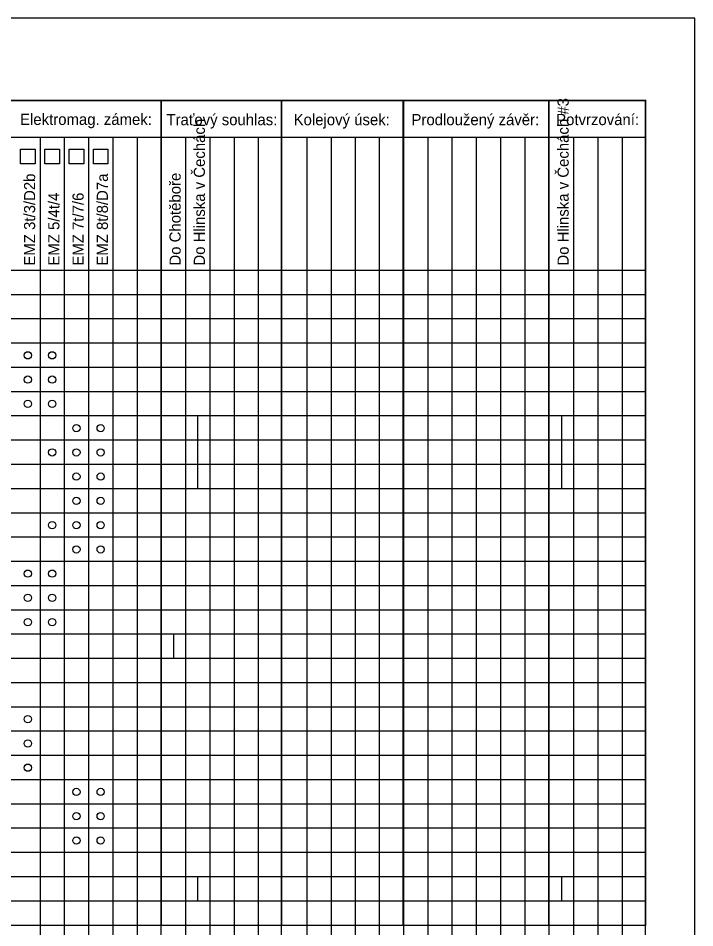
# Model space of a CAD drawing. Extents: x 2343 to 5155, y -3940 to 2050.
# Drawn here: x 4830.5 to 4970, y -3830.5 to -3643 of the extents above; entities that cross this region are included whole.
import ezdxf

# ---------------------------------------------------------------- set-up
doc = ezdxf.new("R2010")
doc.units = 0
for name, color, linetype in [('0B', 7, 'Continuous'), ('Vrstva 1', 7, 'Continuous'), ('Vrstva 63', 7, 'Continuous')]:
    doc.layers.add(name, color=color, linetype=linetype)

# ---------------------------------------------------------------- blocks, each defined once
blk = doc.blocks.new('ZT175')
at = {"layer": 'Vrstva 1'}
blk.add_circle((0, 0), 0.75, dxfattribs=at)

msp = doc.modelspace()

# ---------------------------------------------------------------- linework, layer by layer
for p, q in [((4705, -3667.5), (4959.82, -3667.5)), ((4835, -3667.5), (4835, -3890)), ((4840, -3667.5), (4840, -3890)), ((4845, -3667.5), (4845, -3890)), ((4850, -3667.5), (4850, -3890)), ((4855, -3667.5), (4855, -3890)), ((4860, -3667.5), (4860, -3830)), ((4865, -3667.5), (4865, -3890)), ((4870, -3667.5), (4870, -3890)), ((4875, -3667.5), (4875, -3890)), ((4880, -3667.5), (4880, -3890)), ((4890, -3667.5), (4890, -3890)), ((4895, -3667.5), (4895, -3890)), ((4900, -3667.5), (4900, -3890)), ((4905, -3890), (4905, -3667.5)), ((4915, -3890), (4915, -3667.5)), ((4920, -3890), (4920, -3667.5)), ((4925, -3890), (4925, -3667.5)), ((4930, -3890), (4930, -3667.5)), ((4935, -3890), (4935, -3667.5)), ((4945, -3667.5), (4945, -3890)), ((4950, -3667.5), (4950, -3890)), ((4955, -3667.5), (4955, -3890)), ((4959.82, -3710), (4705, -3710)), ((4959.82, -3710), (4705, -3710)), ((4959.82, -3715), (4705, -3715)), ((4959.82, -3715), (4705, -3715)), ((4959.82, -3720), (4705, -3720)), ((4959.82, -3720), (4705, -3720)), ((4959.82, -3720), (4705, -3720)), ((4959.82, -3725), (4705, -3725)), ((4959.82, -3725), (4705, -3725)), ((4959.82, -3730), (4705, -3730)), ((4959.82, -3735), (4705, -3735)), ((4935, -3735), (4705, -3735)), ((4959.82, -3735), (4705, -3735)), ((4935, -3735), (4705, -3735)), ((4959.82, -3740), (4705, -3740)), ((4959.82, -3740), (4705, -3740)), ((4959.82, -3745), (4705, -3745)), ((4935, -3750), (4705, -3750)), ((4959.82, -3750), (4705, -3750)), ((4935, -3755), (4705, -3755)), ((4959.82, -3755), (4705, -3755)), ((4959.82, -3755), (4705, -3755)), ((4935, -3760), (4705, -3760)), ((4959.82, -3760), (4705, -3760)), ((4959.82, -3765), (4705, -3765)), ((4959.82, -3770), (4705, -3770)), ((4959.82, -3770), (4705, -3770)), ((4959.82, -3775), (4705, -3775)), ((4959.82, -3775), (4705, -3775)), ((4959.82, -3780), (4705, -3780)), ((4959.82, -3785), (4705, -3785)), ((4959.82, -3790), (4705, -3790)), ((4959.82, -3795), (4705, -3795)), ((4959.82, -3800), (4705, -3800)), ((4959.82, -3800), (4705, -3800)), ((4959.82, -3805), (4705, -3805)), ((4959.82, -3810), (4705, -3810)), ((4959.82, -3815), (4705, -3815)), ((4959.82, -3820), (4705, -3820)), ((4959.82, -3825), (4705, -3825)), ((4959.82, -3830), (4705, -3830))]:
    msp.add_line(p, q)
for points in [[(4705, -3660), (4959.82, -3660)], [(4860, -3660), (4860, -3830)], [(4884.82, -3660), (4884.82, -3830)], [(4909.82, -3660), (4909.82, -3830)], [(4939.82, -3660), (4939.82, -3830)], [(4959.82, -3660), (4959.82, -3830)], [(4959.82, -3695), (4705, -3695)], [(4959.82, -3700), (4705, -3700)], [(4959.82, -3705), (4705, -3705)], [(4867.5, -3725.02), (4867.5, -3730.02)], [(4942.5, -3725.02), (4942.5, -3730.02)], [(4867.5, -3730.02), (4867.5, -3735.02)], [(4942.5, -3730.02), (4942.5, -3735.02)], [(4867.5, -3735.02), (4867.5, -3740.02)], [(4942.5, -3735.02), (4942.5, -3740.02)], [(4959.82, -3770), (4585, -3770)], [(4862.5, -3770.02), (4862.5, -3775.02)], [(4959.82, -3775), (4585, -3775)], [(4959.82, -3780), (4585, -3780)], [(4867.5, -3820.02), (4867.5, -3825.02)], [(4942.5, -3820.02), (4942.5, -3825.02)]]:
    msp.add_lwpolyline(points)
for points in [[(4831, -3670), (4834, -3670), (4834, -3673), (4831, -3673)], [(4836, -3670), (4839, -3670), (4839, -3673), (4836, -3673)], [(4841, -3670), (4844, -3670), (4844, -3673), (4841, -3673)], [(4846, -3670), (4849, -3670), (4849, -3673), (4846, -3673)]]:
    msp.add_lwpolyline(points, close=True)
at = {"layer": '0B'}
for points in [[(4960, -3660), (4585, -3660)], [(4860, -3890), (4860, -3660)], [(4884.82, -3890), (4884.82, -3660)], [(4910, -3890), (4910, -3660)], [(4940, -3890), (4940, -3660)], [(4959.82, -3890), (4959.82, -3660)], [(4960, -3695), (4585, -3695)], [(4960, -3700), (4585, -3700)], [(4959.82, -3705), (4585, -3705)], [(4959.82, -3775), (4585, -3775)], [(4959.82, -3780), (4585, -3780)]]:
    msp.add_lwpolyline(points, dxfattribs=at)
at = {"layer": 'Vrstva 63'}
msp.add_lwpolyline([(4550, -3940), (4970, -3940), (4970, -3643), (4550, -3643)], close=True, dxfattribs=at)

# ---------------------------------------------------------------- block references
for p in [(4832.5, -3712.5), (4837.5, -3712.5), (4832.5, -3717.5), (4837.5, -3717.5), (4832.5, -3722.5), (4837.5, -3722.5), (4842.5, -3727.5), (4847.5, -3727.5), (4837.5, -3732.5), (4842.5, -3732.5), (4847.5, -3732.5), (4842.5, -3737.5), (4847.5, -3737.5), (4842.5, -3742.5), (4847.5, -3742.5), (4837.5, -3747.5), (4842.5, -3747.5), (4847.5, -3747.5), (4842.5, -3752.5), (4847.5, -3752.5), (4832.5, -3757.5), (4837.5, -3757.5), (4832.5, -3762.5), (4837.5, -3762.5), (4832.5, -3767.5), (4837.5, -3767.5), (4832.5, -3787.5), (4832.5, -3792.5), (4832.5, -3797.5), (4842.5, -3802.5), (4847.5, -3802.5), (4842.5, -3807.5), (4847.5, -3807.5), (4842.5, -3812.5), (4847.5, -3812.5)]:
    msp.add_blockref('ZT175', p)

# ---------------------------------------------------------------- texts
for s, rotation, p in [('Do Hlinska v Čechách #3', 90, (4944, -3694)), ('Elektromag. zámek:', 360, (4830.89, -3665)), ('Traťový souhlas:', 360, (4861.06, -3665.06)), ('Kolejový úsek:', 360, (4887.29, -3665.06)), ('Prodloužený závěr:', 360, (4911.59, -3665.06)), ('Potvrzování:', 360, (4941.41, -3665.04)), ('Do Hlinska v Čechách', 90, (4869, -3694)), ('EMZ 3t/3/D2b', 90, (4834, -3694)), ('EMZ 8t/8/D7a', 90, (4849, -3694)), ('Do Chotěboře', 90, (4864, -3694)), ('EMZ 5/4t/4', 90, (4839, -3694)), ('EMZ 7t/7/6', 90, (4844, -3694))]:
    msp.add_text(s, height=2.3, rotation=rotation).set_placement(p)

doc.saveas('drawing.dxf')
